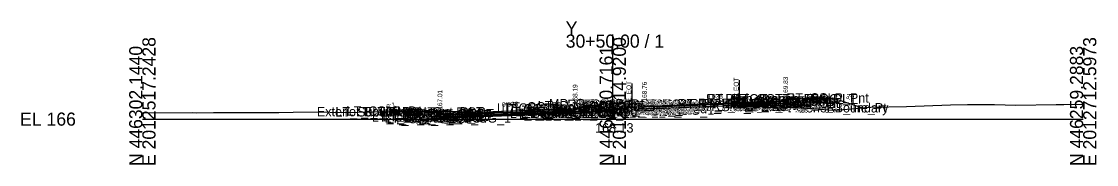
# Model space of a CAD drawing. Extents: x -26 to 3203, y -10 to 9532.
# Drawn here: x 1974.3 to 2202.8, y 4490.3 to 4520.8 of the extents above; entities that cross this region are included whole.
import ezdxf

# ---------------------------------------------------------------- set-up
doc = ezdxf.new("R2010")
doc.units = 0
for name, color, linetype in [('Default', 7, 'Continuous'), ('Exist CMT Pavement', 7, 'Continuous'), ('Exist Cross Section Cell', 7, 'Continuous'), ('Exist XS Center Line Elevation Label', 7, 'Continuous'), ('Exist XS Ground Line', 7, 'Continuous'), ('Prop CMT Conc Surface', 7, 'Continuous'), ('Prop CMT Concrete Structures', 7, 'Continuous'), ('Prop CMT Pvmt Course 1', 7, 'Continuous'), ('Prop CMT Pvmt Course 1 CG', 7, 'Continuous'), ('Prop CMT Pvmt Course 2', 7, 'Continuous'), ('Prop CMT Pvmt Course 3', 7, 'Continuous'), ('Prop CMT Pvmt Surface', 7, 'Continuous'), ('Prop CMT Pvmt Wedge Surface 2', 7, 'Continuous'), ('Prop CMT Pvmt Wedge Surface 3', 7, 'Continuous'), ('Prop CMT Slope Grass', 7, 'Continuous'), ('Prop CMT Subgrade Earthwork', 7, 'Continuous'), ('Prop XS Hydro Elevations', 7, 'Continuous'), ('Prop XS Label Text', 7, 'Continuous'), ('Prop XS SE Text', 7, 'Continuous'), ('Prop XS Side Slope Text', 7, 'Continuous'), ('Scratch_Level_0', 7, 'Continuous')]:
    doc.layers.add(name, color=color, linetype=linetype)

msp = doc.modelspace()

# ---------------------------------------------------------------- linework, layer by layer
at = {"layer": 'Exist CMT Pavement'}
msp.add_lwpolyline([(2104.03, 4502.58), (2104.03, 4502.58), (2104.72, 4502.6), (2105.18, 4502.62), (2107.28, 4502.69), (2108.46, 4502.73), (2109.84, 4502.77), (2111.73, 4502.82), (2112.4, 4502.83), (2112.82, 4502.84), (2114.97, 4502.9), (2115.35, 4502.91), (2116.5, 4502.96), (2117.48, 4502.99), (2118.26, 4503.02), (2120.04, 4503.09), (2121.17, 4503.12), (2122.6, 4503.16), (2123.28, 4503.18), (2125.16, 4503.24), (2125.6, 4503.25), (2126.84, 4503.28)], dxfattribs=at)
at = {"layer": 'Exist Cross Section Cell'}
for p, q in [((2100, 4500), (2100, 4518.03)), ((2000, 4500), (2100, 4500)), ((2100, 4500), (2200, 4500))]:
    msp.add_line(p, q, dxfattribs=at)
at = {"layer": 'Exist XS Ground Line'}
msp.add_lwpolyline([(2000, 4501.35), (2010.61, 4501.38), (2011.6, 4501.37), (2015.1, 4501.39), (2021.84, 4501.42), (2029.02, 4501.4), (2032.08, 4501.48), (2037.42, 4501.52), (2042.32, 4501.43), (2045.82, 4501.45), (2052.55, 4501.6), (2054.21, 4501.59), (2061.78, 4501.66), (2062.79, 4501.66), (2075.6, 4501.49), (2079.86, 4501.36), (2086.55, 4501.06), (2086.89, 4501.04), (2087.54, 4501.08), (2094.04, 4501.39), (2100, 4502.13), (2102.11, 4502.39), (2103.08, 4502.5), (2103.58, 4502.55), (2104.03, 4502.58), (2104.72, 4502.6), (2105.18, 4502.62), (2107.28, 4502.69), (2108.46, 4502.73), (2109.84, 4502.77), (2111.73, 4502.82), (2112.4, 4502.83), (2112.82, 4502.84), (2114.97, 4502.9), (2115.35, 4502.91), (2116.5, 4502.96), (2117.48, 4502.99), (2118.26, 4503.02), (2120.04, 4503.09), (2121.17, 4503.12), (2122.6, 4503.16), (2123.28, 4503.18), (2125.16, 4503.24), (2125.6, 4503.25), (2126.84, 4503.28), (2127.7, 4503.3), (2128.87, 4503.29), (2142.31, 4502.24), (2144.98, 4502.02), (2146.96, 4501.88), (2148.11, 4502), (2154.85, 4502.57), (2162.43, 4502.69), (2171.77, 4503.07), (2175.42, 4503.09), (2181.13, 4503.08), (2185.66, 4502.98), (2194.24, 4503.1), (2195.9, 4503.14), (2200, 4503.18)], dxfattribs=at)
at = {"layer": 'Prop CMT Conc Surface'}
for points in [[(2141.25, 4504.42), (2146.25, 4504.52)], [(2091.25, 4502.16), (2092, 4502.19), (2092, 4502.36), (2092.76, 4502.61)], [(2108.75, 4502.84), (2106.75, 4502.76), (2106.75, 4502.93), (2106, 4503.18)], [(2134.75, 4503.83), (2136.75, 4503.83)], [(2136.75, 4503.83), (2136.75, 4504.33), (2137.25, 4504.33)], [(2058.75, 4501.6), (2053.75, 4501.7)], [(2063.25, 4501.01), (2063.25, 4501.51), (2062.75, 4501.51)], [(2065.25, 4501.17), (2063.25, 4501.01)]]:
    msp.add_lwpolyline(points, dxfattribs=at)
at = {"layer": 'Prop CMT Concrete Structures'}
for points in [[(2146.25, 4504.52), (2141.25, 4504.42)], [(2141.25, 4504.42), (2141.25, 4504.09)], [(2146.25, 4504.19), (2146.25, 4504.52)], [(2091.25, 4502.16), (2092, 4502.19), (2092, 4502.36), (2092.76, 4502.61)], [(2091.25, 4501.58), (2091.25, 4502.16)], [(2092.76, 4502.61), (2092.76, 4501.64)], [(2108.75, 4502.84), (2106.75, 4502.76), (2106.75, 4502.93), (2106, 4503.18)], [(2106, 4503.18), (2106, 4502.15)], [(2106, 4502.15), (2108.75, 4502.25)], [(2108.75, 4502.25), (2108.75, 4502.84)], [(2134.75, 4503.83), (2136.75, 4503.83), (2136.75, 4504.33), (2137.25, 4504.33)], [(2137.25, 4504.33), (2137.25, 4503.35), (2134.75, 4503.25)], [(2134.75, 4503.25), (2134.75, 4503.83)], [(2141.25, 4504.09), (2146.25, 4504.19)], [(2053.75, 4501.37), (2053.75, 4501.7)], [(2053.75, 4501.7), (2058.75, 4501.6)], [(2058.75, 4501.27), (2053.75, 4501.37)], [(2058.75, 4501.6), (2058.75, 4501.27)], [(2065.25, 4501.17), (2063.25, 4501.01), (2063.25, 4501.51), (2062.75, 4501.51)], [(2062.75, 4501.51), (2062.75, 4500.49), (2065.25, 4500.58)], [(2065.25, 4500.58), (2065.25, 4501.17)], [(2092.76, 4501.64), (2091.25, 4501.58)]]:
    msp.add_lwpolyline(points, dxfattribs=at)
at = {"layer": 'Prop CMT Pvmt Course 1'}
for points in [[(2091.25, 4502.16), (2065.25, 4501.17)], [(2091.25, 4501.91), (2091.25, 4502.16)], [(2108.75, 4502.84), (2134.75, 4503.83)], [(2108.75, 4502.59), (2108.75, 4502.84)], [(2108.75, 4502.59), (2108.75, 4502.59)], [(2134.75, 4503.83), (2134.75, 4503.58)], [(2065.25, 4500.92), (2091.25, 4501.91)], [(2065.25, 4501.17), (2065.25, 4500.92)], [(2091.25, 4501.91), (2091.25, 4501.91), (2091.25, 4501.91)]]:
    msp.add_lwpolyline(points, dxfattribs=at)
at = {"layer": 'Prop CMT Pvmt Course 1 CG'}
for points in [[(2108.75, 4502.25), (2105.5, 4502.13), (2105.15, 4501.78)], [(2108.75, 4501.92), (2108.75, 4502.25)], [(2134.75, 4503.25), (2137.75, 4503.36), (2138.07, 4503.04)], [(2134.75, 4502.92), (2134.75, 4503.25)], [(2138.07, 4503.04), (2134.75, 4502.92)], [(2065.25, 4500.58), (2062.25, 4500.47), (2061.9, 4500.12)], [(2061.9, 4500.12), (2065.25, 4500.25)], [(2065.25, 4500.25), (2065.25, 4500.58)], [(2091.25, 4501.58), (2093.26, 4501.66), (2093.58, 4501.34)], [(2091.25, 4501.25), (2091.25, 4501.58)], [(2093.58, 4501.34), (2091.25, 4501.25)], [(2105.15, 4501.78), (2108.75, 4501.92)]]:
    msp.add_lwpolyline(points, dxfattribs=at)
at = {"layer": 'Prop CMT Pvmt Course 2'}
msp.add_lwpolyline([(2108.75, 4502.59), (2108.75, 4502.25), (2108.75, 4502.25)], close=True, dxfattribs=at)
for points in [[(2108.75, 4502.59), (2108.75, 4502.59)], [(2126.84, 4503.28), (2134.75, 4503.58)], [(2126.84, 4502.95), (2126.84, 4503.28)], [(2134.75, 4503.25), (2126.84, 4502.95)], [(2134.75, 4503.58), (2134.75, 4503.25)], [(2091.25, 4501.91), (2065.25, 4500.92)], [(2065.25, 4500.58), (2091.25, 4501.58)], [(2065.25, 4500.92), (2065.25, 4500.58)], [(2091.25, 4501.58), (2091.25, 4501.91)]]:
    msp.add_lwpolyline(points, dxfattribs=at)
at = {"layer": 'Prop CMT Pvmt Course 3'}
for points in [[(2108.75, 4502.25), (2108.75, 4502.25), (2108.75, 4501.92), (2108.75, 4501.92)], [(2108.75, 4501.92), (2108.75, 4502.25)], [(2126.84, 4502.95), (2134.75, 4503.25)], [(2126.84, 4502.61), (2126.84, 4502.95)], [(2134.75, 4502.92), (2126.84, 4502.61)], [(2134.75, 4503.25), (2134.75, 4502.92)], [(2091.25, 4501.58), (2065.25, 4500.58)], [(2065.25, 4500.25), (2091.25, 4501.25)], [(2065.25, 4500.58), (2065.25, 4500.25)], [(2091.25, 4501.25), (2091.25, 4501.58)]]:
    msp.add_lwpolyline(points, dxfattribs=at)
at = {"layer": 'Prop CMT Pvmt Surface'}
for points in [[(2091.25, 4502.16), (2065.25, 4501.17)], [(2108.75, 4502.84), (2134.75, 4503.83)]]:
    msp.add_lwpolyline(points, dxfattribs=at)
at = {"layer": 'Prop CMT Pvmt Wedge Surface 2'}
msp.add_lwpolyline([(2108.75, 4502.59), (2134.75, 4503.58)], dxfattribs=at)
at = {"layer": 'Prop CMT Pvmt Wedge Surface 3'}
msp.add_lwpolyline([(2108.75, 4502.25), (2134.75, 4503.25)], dxfattribs=at)
at = {"layer": 'Prop CMT Slope Grass'}
for points in [[(2137.25, 4504.33), (2146.75, 4504.52)], [(2146.75, 4504.52), (2153.06, 4502.42)], [(2092.76, 4502.61), (2099.38, 4503.31)], [(2106, 4503.18), (2099.38, 4503.31)], [(2053.25, 4501.7), (2052.94, 4501.6)], [(2062.75, 4501.51), (2053.25, 4501.7)]]:
    msp.add_lwpolyline(points, dxfattribs=at)
at = {"layer": 'Prop CMT Subgrade Earthwork'}
for points in [[(2095.1, 4502.86), (2093.58, 4501.34)], [(2103.71, 4503.22), (2105.15, 4501.78)], [(2108.75, 4501.92), (2108.73, 4502.73)], [(2126.84, 4502.61), (2126.86, 4503.28)], [(2126.84, 4502.61), (2134.75, 4502.92)], [(2134.75, 4502.92), (2138.07, 4503.04), (2139.4, 4504.37)], [(2134.75, 4502.92), (2134.75, 4502.92)], [(2065.25, 4500.25), (2061.9, 4500.12), (2060.47, 4501.55)], [(2091.25, 4501.25), (2065.25, 4500.25)], [(2065.25, 4500.25), (2065.25, 4500.25)], [(2093.58, 4501.34), (2091.25, 4501.25)], [(2091.25, 4501.25), (2091.25, 4501.25)], [(2091.25, 4501.25), (2091.25, 4501.25)], [(2105.15, 4501.78), (2108.75, 4501.92)], [(2108.75, 4501.92), (2108.75, 4501.92)], [(2108.75, 4501.92), (2108.75, 4501.92)]]:
    msp.add_lwpolyline(points, dxfattribs=at)
at = {"layer": 'Prop XS Label Text'}
for p, q in [((2104.03, 4507.58), (2104.03, 4502.58)), ((2126.84, 4508.28), (2126.84, 4503.28))]:
    msp.add_line(p, q, dxfattribs=at)

# ---------------------------------------------------------------- texts
at = {"layer": 'Default'}
msp.add_text('-', height=0.0001, dxfattribs=at).set_placement((2000, 4500))
at = {"layer": 'Exist Cross Section Cell'}
for s, p in [('Y', (2090, 4518.03)), ('30+50.00 / 1', (2090, 4515.23)), ('EL 166', (1974, 4498.6))]:
    msp.add_text(s, height=2.8, dxfattribs=at).set_placement(p)
for s, p in [('E 2012517.2428', (2002.8, 4490)), ('E 2012614.9200', (2102.8, 4490)), ('E 2012712.5973', (2202.8, 4490)), ('N 446302.1440', (2000, 4490)), ('N 446280.7161', (2100, 4490)), ('N 446259.2883', (2200, 4490))]:
    msp.add_text(s, height=2.8, rotation=90, dxfattribs=at).set_placement(p)
at = {"layer": 'Exist XS Center Line Elevation Label'}
msp.add_text('168.13', height=2, dxfattribs=at).set_placement((2096.23, 4497.13))
at = {"layer": 'Prop XS Hydro Elevations'}
for s, p in [('168.19', (2092.5, 4503.19)), ('168.76', (2107.25, 4503.76)), ('169.83', (2137.25, 4504.83)), ('167.01', (2063.75, 4502.01))]:
    msp.add_text(s, height=1, rotation=90, dxfattribs=at).set_placement(p)
at = {"layer": 'Prop XS Label Text'}
for p in [(2103.93, 4503.61), (2126.74, 4504.31)]:
    msp.add_text('E. EOT', height=1, rotation=90, dxfattribs=at).set_placement(p)
at = {"layer": 'Prop XS SE Text'}
for p in [(2119.97, 4504.27), (2076.47, 4502.6)]:
    msp.add_text('0.038', height=1, rotation=2.1978, dxfattribs=at).set_placement(p)
at = {"layer": 'Prop XS Side Slope Text'}
for rotation, p in [(341.5651, (2149.46, 4504.47)), (18.4349, (2052.11, 4502.11))]:
    msp.add_text('3:1', height=1, rotation=rotation, dxfattribs=at).set_placement(p)
at = {"layer": 'Scratch_Level_0'}
for s, p in [('MD_Crown Point', (2086.45, 4502.31)), ('RT_PV_Sub_Tie_Out', (2113.78, 4502.29)), ('RT_PV2_OEEOP', (2118.13, 4502.36)), ('RT_Sub_Trench_Out_DLT', (2119.92, 4503.37)), ('RT_CG_Top_Face', (2123.96, 4503.33)), ('RT_CG1_Shelf_Out', (2124.25, 4502.36)), ('RT_PV2_OEOT', (2124.88, 4502.58)), ('RT_CG_Top_Gut', (2124.94, 4502.83)), ('RT_PV1_OEOT', (2125.44, 4502.83)), ('RT_CG_Top_BOC', (2125.49, 4503.33)), ('RT_CSLP_Pnt', (2136.88, 4503.52)), ('Exterior Boundary', (2037.09, 4500.6)), ('LT_Sub_Trench_Out_DLT', (2041.04, 4500.55)), ('LT_CSLP_Pnt', (2043.42, 4500.7)), ('LT_Tie_Pt', (2045.39, 4500.6)), ('LT_CG_Top_Face', (2050.51, 4500.51)), ('LT_CG_Top_BOC', (2051.03, 4500.51)), ('LT_PV1_OEOT', (2055.99, 4500.17)), ('LT_CG_Top_Face_Med', (2075.37, 4501.36)), ('LT_CG_Top_Gut_Med', (2076.35, 4501.19)), ('LT_CG_Top_BOC_Med', (2077.15, 4501.61)), ('LT_CG_Bot_BOC_Med', (2077.19, 4500.64)), ('LT_CG_Bot_IE_Med', (2077.31, 4500.58)), ('LT_Sub_IEOT_CG_1', (2078.12, 4500.25)), ('LT_Sub_OEEOP', (2080.46, 4500.25)), ('LT_PV2_OEEOP', (2080.56, 4500.91)), ('LT_PV3_OEEOP', (2080.56, 4500.58)), ('LT_Sub_IEEOP', (2081.11, 4500.25)), ('LT_PV2_IEEOP', (2081.2, 4500.91)), ('LT_CG1_Shelf_In', (2081.43, 4500.66)), ('LT_Sub_PGL', (2082.37, 4500.25)), ('LT_PV2_PGL', (2082.46, 4500.91)), ('LT_PV1_PGL', (2083.03, 4501.16)), ('LT_Sub_DLT_In', (2084.05, 4501.86)), ('LT_Sub_IEOP', (2084.34, 4500.34)), ('RT_CG_Top_BOC_Med', (2090.35, 4502.18)), ('RT_CG_Bot BOC In', (2091.84, 4501.15)), ('RT_CG_Top_BOC In', (2091.97, 4502.18)), ('RT_Sub_DLT_In', (2092.61, 4502.22)), ('RT_CG_Top FOC In', (2092.61, 4501.93)), ('RT_CG_Top_Gut In', (2092.64, 4501.76)), ('RT_CG1_Shelf_In', (2093.63, 4501.13)), ('RT_CG_Bot_IE_Med', (2094.77, 4501.25)), ('RT_PV_Sub_Tie_In', (2095.25, 4501.73)), ('RT_Sub_IEOT_CG_1', (2095.57, 4500.92)), ('RT_Sub_IEOP', (2095.86, 4500.78)), ('RT_PV_IEEOP_EG', (2096.89, 4501.73)), ('RT_Sub_IEEOP', (2098.56, 4500.92)), ('RT_PV2_IEEOP', (2098.66, 4501.59)), ('RT_PV3_IEEOP', (2098.66, 4501.25)), ('RT_Sub_PGL', (2099.82, 4500.92)), ('RT_PV2_PGL', (2099.92, 4501.59)), ('RT_PV3_PGL', (2099.92, 4501.25)), ('RT_PV1_PGL', (2100.48, 4501.84)), ('RT_PV_OEEOP_EG', (2116.36, 4502.29)), ('RT_Sub_OEEOP', (2118.03, 4501.69)), ('RT_PV3_OEEOP', (2118.13, 4502.02)), ('RT_Sub_OEOT_CG_1', (2120.92, 4501.92)), ('RT_CG_Bot_IE', (2124.62, 4502.25)), ('RT_Sub_OEOT', (2124.78, 4501.92)), ('RT_PV3_OEOT', (2124.88, 4502.25)), ('RT_CG_Bot_BOC', (2125.52, 4502.35)), ('RT_Sub_OEOP', (2128.13, 4502.04)), ('Exterior Boundary', (2137.2, 4501.42)), ('RT_Tie_Pt', (2145.45, 4501.42)), ('LT_CG1_Shelf_Out', (2048.8, 4499.47)), ('LT_CG_Bot_BOC', (2051.06, 4499.49)), ('LT_Sub_OEOT_CG_1', (2051.47, 4499.25)), ('LT_CG_Top_Gut', (2051.49, 4500.01)), ('LT_Sub_OEOP', (2052.01, 4499.12)), ('LT_CG_Bot_IE', (2055.16, 4499.58)), ('LT_Sub_OEOT', (2055.33, 4499.25)), ('LT_PV2_OEOT', (2055.42, 4499.92)), ('LT_PV3_OEOT', (2055.42, 4499.58))]:
    msp.add_text(s, height=2, dxfattribs=at).set_placement(p)

doc.saveas('drawing.dxf')
